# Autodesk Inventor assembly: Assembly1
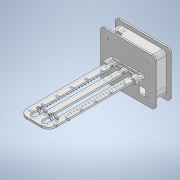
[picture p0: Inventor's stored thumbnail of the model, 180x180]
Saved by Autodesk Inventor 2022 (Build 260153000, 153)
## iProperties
Created: 2022-12
Part Number: Assembly1
Document SubType Name: Assembly
Designer: suerfu
Author: suerfu
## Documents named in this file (5)
- C:\Users\suerfu\Documents\Nixie Thermometer\Assembly1.iam
- C:\Users\suerfu\Documents\Nixie Thermometer\base_bottom.ipt
- C:\Users\suerfu\Documents\Nixie Thermometer\base_top.ipt
- C:\Users\suerfu\Documents\Nixie Thermometer\frame.ipt
- C:\Users\suerfu\Documents\Nixie Thermometer\clamp_9p2mm.ipt
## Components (5 placed, 4 different names)
1. base_bottom:1 — Mate:1, Mate:2, Mate:3
2. base_top:1 — Mate:1, Mate:2, Mate:3, Mate:5, Mate:6, Flush:1
3. frame:1 — Mate:5, Mate:6, Flush:1, Mate:9, Mate:8, Mate:7, Flush:3, Flush:4
4. clamp_9p2mm:1 — Flush:2, Mate:8, Mate:7, Flush:3
5. clamp_9p2mm:2 — Flush:2, Mate:9, Flush:4
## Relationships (12: Mate 8, Flush 4)
- Mate:1: base_bottom:1 ↔ base_top:1
- Mate:2: base_bottom:1 ↔ base_top:1
- Mate:3: base_bottom:1 ↔ base_top:1
- Mate:5: base_top:1 ↔ frame:1
- Mate:6: base_top:1 ↔ frame:1
- Flush:1: base_top:1 ↔ frame:1
- Flush:2: clamp_9p2mm:1 ↔ clamp_9p2mm:2
- Mate:9: frame:1 ↔ clamp_9p2mm:2
- Mate:8: frame:1 ↔ clamp_9p2mm:1
- Mate:7: frame:1 ↔ clamp_9p2mm:1
- Flush:3: frame:1 ↔ clamp_9p2mm:1
- Flush:4: frame:1 ↔ clamp_9p2mm:2
